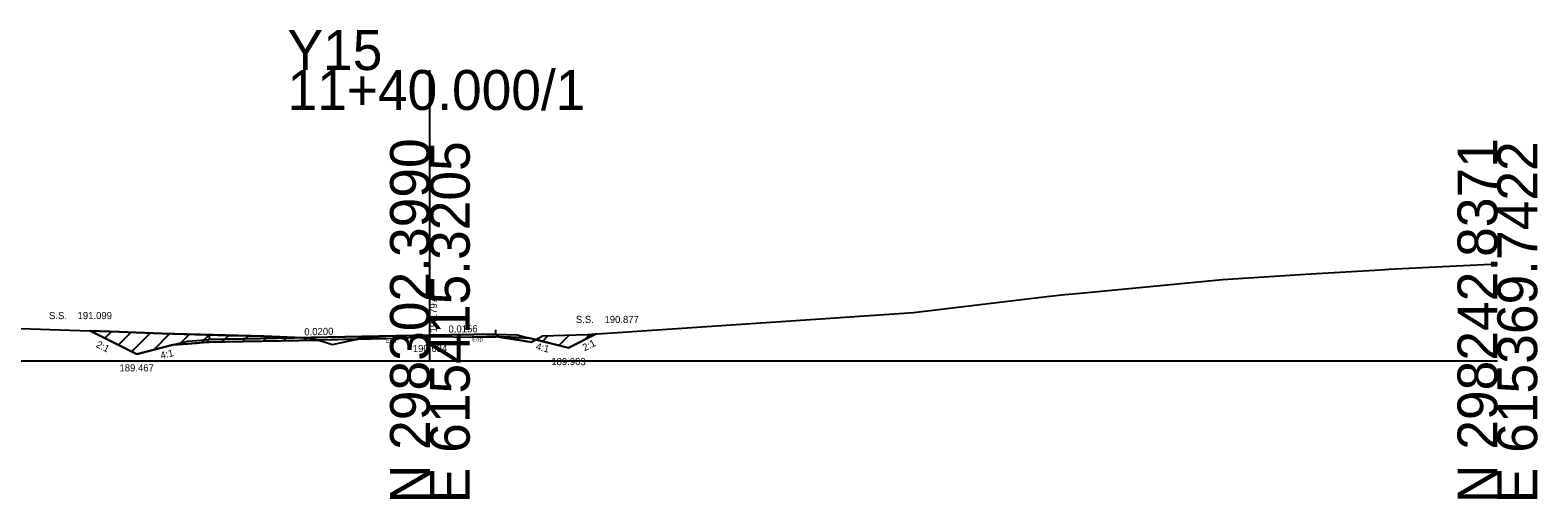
# Model space of a CAD drawing. Extents: x 517327 to 517505, y 114839 to 116885.
# Drawn here: x 517399.3 to 517505.2, y 114838.7 to 114871.6 of the extents above; entities that cross this region are included whole.
import ezdxf

# ---------------------------------------------------------------- set-up
doc = ezdxf.new("R2010")
doc.units = 0
for name, color, linetype in [('Exist XS Ground Line', 7, 'Continuous'), ('Old_Level_60', 7, 'Continuous'), ('Old_Level_63', 7, 'Continuous'), ('Prop XS Dump Level', 7, 'Continuous'), ('Prop XS Earthwork Shape', 7, 'Continuous'), ('Prop XS Elevation Labels', 7, 'Continuous'), ('Prop XS EOT Tick Mark', 7, 'Continuous'), ('Prop XS Finish Grade', 7, 'Continuous'), ('Prop XS Finish Grade Earthwork', 7, 'Continuous'), ('Prop XS Finish Grade Pavement', 7, 'Continuous'), ('Prop XS Hydro Elevations', 7, 'Continuous'), ('Prop XS Label Text', 7, 'Continuous'), ('Prop XS Pvmt Edge Slope', 7, 'Continuous'), ('Prop XS SE Text', 7, 'Continuous'), ('Prop XS Side Slope Text', 7, 'Continuous'), ('Prop XS Subgrade Earthwork', 7, 'Continuous'), ('Prop XS Suitable Common Exc Shape', 7, 'Continuous'), ('Scratch_Level_0', 7, 'Continuous')]:
    doc.layers.add(name, color=color, linetype=linetype)

msp = doc.modelspace()

# ---------------------------------------------------------------- linework, layer by layer
at = {"layer": 'Exist XS Ground Line'}
for p, q in [((517489.26, 114854.45), (517494.16, 114854.74)), ((517494.16, 114854.74), (517494.73, 114854.78)), ((517494.73, 114854.78), (517497.56, 114854.92)), ((517497.56, 114854.92), (517502.36, 114855.16)), ((517473.07, 114853.11), (517483.06, 114854.07)), ((517483.06, 114854.07), (517489.26, 114854.45)), ((517461.33, 114851.75), (517470.71, 114852.86)), ((517470.71, 114852.86), (517471.98, 114853)), ((517471.98, 114853), (517473.07, 114853.11)), ((517454.81, 114851.31), (517461.33, 114851.75)), ((517397.92, 114850.65), (517405.53, 114850.4)), ((517405.53, 114850.4), (517408.53, 114850.28)), ((517408.53, 114850.28), (517413.22, 114850.13)), ((517438.44, 114850.2), (517445.09, 114850.65)), ((517445.09, 114850.65), (517448.53, 114850.87)), ((517448.53, 114850.87), (517454.81, 114851.31)), ((517413.22, 114850.13), (517415.69, 114850.09)), ((517415.69, 114850.09), (517418.98, 114849.95)), ((517418.98, 114849.95), (517419.85, 114849.7)), ((517419.85, 114849.7), (517420.5, 114849.49)), ((517420.5, 114849.49), (517421.29, 114849.66)), ((517421.29, 114849.66), (517422.43, 114849.92)), ((517422.43, 114849.92), (517423.92, 114849.91)), ((517423.92, 114849.91), (517424.27, 114849.91)), ((517424.27, 114849.91), (517426.98, 114850.03)), ((517426.98, 114850.03), (517427.38, 114850.05)), ((517427.38, 114850.05), (517427.74, 114850.05)), ((517427.74, 114850.05), (517430.34, 114850.02)), ((517430.34, 114850.02), (517431.86, 114850.09)), ((517431.86, 114850.09), (517434.51, 114849.67)), ((517434.51, 114849.67), (517435.27, 114850.11)), ((517435.27, 114850.11), (517438.44, 114850.2))]:
    msp.add_line(p, q, dxfattribs=at)
at = {"layer": 'Old_Level_63'}
for p, q in [((517427.36, 114848.36), (517427.36, 114868.76)), ((517352.36, 114848.36), (517427.36, 114848.36)), ((517427.36, 114848.36), (517502.36, 114848.36))]:
    msp.add_line(p, q, dxfattribs=at)
at = {"layer": 'Prop XS Dump Level'}
for p, q in [((517411.86, 114849.85), (517427.36, 114850.16)), ((517427.36, 114850.16), (517431.99, 114850.23))]:
    msp.add_line(p, q, dxfattribs=at)
at = {"layer": 'Prop XS Earthwork Shape'}
for points in [[(517403.5, 114850.46), (517405.53, 114850.4), (517408.53, 114850.28), (517413.22, 114850.13), (517415.69, 114850.09), (517418.98, 114849.95), (517419.46, 114849.81), (517411.86, 114849.66), (517411.67, 114849.66), (517410.36, 114849.55), (517409.31, 114849.47), (517406.76, 114848.83)], [(517419.46, 114849.81), (517419.85, 114849.7), (517420.5, 114849.49), (517421.29, 114849.66), (517422.2, 114849.87)], [(517422.2, 114849.87), (517424.26, 114849.91), (517423.92, 114849.91), (517422.43, 114849.92)], [(517431.86, 114850.09), (517432.17, 114850.05), (517431.99, 114850.04), (517430.34, 114850.02)], [(517432.17, 114850.05), (517434.51, 114849.67), (517434.81, 114849.84), (517434.36, 114849.95), (517433.49, 114849.99)], [(517434.81, 114849.84), (517435.27, 114850.11), (517438.44, 114850.2), (517439.04, 114850.24), (517437.09, 114849.27)]]:
    msp.add_lwpolyline(points, close=True, dxfattribs=at)
at = {"layer": 'Prop XS EOT Tick Mark'}
for p, q in [((517431.99, 114850.23), (517431.99, 114850.54)), ((517411.86, 114850.16), (517411.86, 114849.85))]:
    msp.add_line(p, q, dxfattribs=at)
at = {"layer": 'Prop XS Finish Grade'}
for p, q in [((517409.31, 114849.47), (517410.36, 114849.73)), ((517410.36, 114849.73), (517411.86, 114849.85)), ((517431.99, 114850.23), (517433.49, 114850.17)), ((517433.49, 114850.17), (517434.36, 114849.95))]:
    msp.add_line(p, q, dxfattribs=at)
at = {"layer": 'Prop XS Finish Grade Earthwork'}
for p, q in [((517403.5, 114850.46), (517406.76, 114848.83)), ((517406.76, 114848.83), (517409.31, 114849.47)), ((517434.36, 114849.95), (517437.09, 114849.27)), ((517437.09, 114849.27), (517439.04, 114850.24))]:
    msp.add_line(p, q, dxfattribs=at)
at = {"layer": 'Prop XS Finish Grade Pavement'}
for p, q in [((517427.36, 114850.16), (517411.86, 114849.85)), ((517431.99, 114850.23), (517427.36, 114850.16))]:
    msp.add_line(p, q, dxfattribs=at)
at = {"layer": 'Prop XS Pvmt Edge Slope'}
for p, q in [((517411.67, 114849.66), (517411.86, 114849.85)), ((517431.99, 114850.23), (517432.17, 114850.05))]:
    msp.add_line(p, q, dxfattribs=at)
at = {"layer": 'Prop XS Subgrade Earthwork'}
for p, q in [((517409.31, 114849.47), (517410.36, 114849.55)), ((517410.36, 114849.55), (517411.67, 114849.66)), ((517411.67, 114849.66), (517411.86, 114849.66)), ((517411.86, 114849.66), (517424.26, 114849.91)), ((517424.26, 114849.91), (517424.26, 114849.91)), ((517430.34, 114850.02), (517431.99, 114850.04)), ((517430.34, 114850.02), (517430.34, 114850.02)), ((517431.99, 114850.04), (517432.17, 114850.05)), ((517432.17, 114850.05), (517433.49, 114849.99)), ((517433.49, 114849.99), (517434.36, 114849.95))]:
    msp.add_line(p, q, dxfattribs=at)
at = {"layer": 'Prop XS Suitable Common Exc Shape'}
for points in [[(517418.98, 114849.95), (517419.47, 114849.81), (517411.86, 114849.66), (517411.67, 114849.66), (517410.36, 114849.55), (517409.31, 114849.47), (517406.76, 114848.83), (517403.5, 114850.46), (517405.53, 114850.4), (517408.53, 114850.28), (517413.22, 114850.13), (517415.69, 114850.09)], [(517421.29, 114849.66), (517422.18, 114849.86), (517419.47, 114849.81), (517419.85, 114849.7), (517420.5, 114849.49)], [(517423.92, 114849.91), (517424.27, 114849.91), (517422.18, 114849.86), (517422.43, 114849.92)], [(517431.86, 114850.09), (517432.17, 114850.05), (517431.99, 114850.04), (517430.34, 114850.02)], [(517434.36, 114849.95), (517434.81, 114849.84), (517434.51, 114849.67), (517432.17, 114850.05), (517433.49, 114849.99)], [(517438.44, 114850.2), (517439.04, 114850.24), (517437.09, 114849.27), (517434.81, 114849.84), (517435.27, 114850.11)]]:
    msp.add_lwpolyline(points, close=True, dxfattribs=at)
at = {"layer": 'Scratch_Level_0'}
for p, q in [((517403.59, 114850.42), (517403.63, 114850.46)), ((517404.53, 114849.95), (517405, 114850.41)), ((517405.48, 114849.47), (517406.37, 114850.36)), ((517406.42, 114849), (517407.73, 114850.31)), ((517407.96, 114849.13), (517409.1, 114850.27)), ((517409.75, 114849.5), (517410.47, 114850.23)), ((517411.29, 114849.63), (517411.85, 114850.19)), ((517412.75, 114849.68), (517413.23, 114850.15)), ((517414.2, 114849.71), (517414.61, 114850.12)), ((517415.64, 114849.73), (517415.98, 114850.08)), ((517417.08, 114849.76), (517417.34, 114850.02)), ((517418.52, 114849.79), (517418.7, 114849.97)), ((517435.29, 114849.74), (517435.68, 114850.12)), ((517436.41, 114849.44), (517437.14, 114850.16)), ((517438.22, 114849.83), (517438.6, 114850.21))]:
    msp.add_line(p, q, dxfattribs=at)
for points in [[(517403.5, 114850.46), (517406.76, 114848.83), (517409.31, 114849.47), (517410.96, 114849.6), (517411.67, 114849.66), (517419.47, 114849.81), (517418.98, 114849.95), (517415.69, 114850.09), (517408.53, 114850.28), (517405.53, 114850.4)], [(517439.04, 114850.24), (517437.09, 114849.27), (517434.81, 114849.84), (517435.27, 114850.11), (517438.44, 114850.2)]]:
    msp.add_lwpolyline(points, close=True, dxfattribs=at)

# ---------------------------------------------------------------- texts
at = {"layer": 'Old_Level_60'}
msp.add_text('190.684', height=0.5, dxfattribs=at).set_placement((517426.16, 114848.97))
at = {"layer": 'Old_Level_63'}
for s, p in [('Y15', (517417.36, 114868.76)), ('11+40.000/1', (517417.36, 114865.96))]:
    msp.add_text(s, height=2.8, dxfattribs=at).set_placement(p)
for s, p in [('N 298302.3990', (517427.36, 114838.36)), ('E 615415.3205', (517430.16, 114838.36)), ('N 298242.8371', (517502.36, 114838.37)), ('E 615369.7422', (517505.16, 114838.36))]:
    msp.add_text(s, height=2.8, rotation=90, dxfattribs=at).set_placement(p)
at = {"layer": 'Prop XS Dump Level'}
for s, height, p in [('Case1', 0.0122, (517410.36, 114849.72)), ('Eop', 0.3, (517424.26, 114849.61)), ('Eop', 0.3, (517430.34, 114849.72)), ('Case1', 0.0122, (517433.49, 114850.16))]:
    msp.add_text(s, height=height, dxfattribs=at).set_placement(p)
at = {"layer": 'Prop XS Elevation Labels'}
msp.add_text(' 190.797', height=0.5, rotation=90, dxfattribs=at).set_placement((517427.86, 114850.16))
at = {"layer": 'Prop XS Hydro Elevations'}
for s, p in [('S.S.    191.099', (517400.6, 114851.28)), ('S.S.    190.877', (517437.62, 114851.01))]:
    msp.add_text(s, height=0.5, dxfattribs=at).set_placement(p)
at = {"layer": 'Prop XS Label Text'}
for rotation, p in [(345.9638, (517434.77, 114849.15)), (14.0362, (517408.49, 114848.47))]:
    msp.add_text('4:1', height=0.5, rotation=rotation, dxfattribs=at).set_placement(p)
at = {"layer": 'Prop XS SE Text'}
for s, rotation, p in [('0.0200', 1.1458, (517418.54, 114850.14)), ('0.0156', 0.8958, (517428.67, 114850.33))]:
    msp.add_text(s, height=0.5, rotation=rotation, dxfattribs=at).set_placement(p)
at = {"layer": 'Prop XS Side Slope Text'}
for rotation, p in [(333.435, (517403.86, 114849.34)), (26.5651, (517438.23, 114849.02))]:
    msp.add_text('2:1', height=0.5, rotation=rotation, dxfattribs=at).set_placement(p)
for s, p in [('189.903', (517435.89, 114848.05)), ('189.467', (517405.55, 114847.61))]:
    msp.add_text(s, height=0.5, dxfattribs=at).set_placement(p)

doc.saveas('drawing.dxf')
